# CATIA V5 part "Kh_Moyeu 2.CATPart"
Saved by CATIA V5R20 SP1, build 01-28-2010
Part number: Moyeu 2
Bounding box of the stored display mesh (mm): x -31.991 to 31.991, y -32 to 32, z -27 to 27
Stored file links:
  G:\Khaled_CFAO_2011\SIL\SIL_GR1\tmerino\Khaled\CAD_Thinkmotion\Kh_Moyeu 2.CATPart
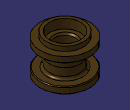
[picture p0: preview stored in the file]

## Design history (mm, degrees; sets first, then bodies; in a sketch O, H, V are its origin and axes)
Body1 (main body)
  Sketch1 on yz-plane, origin (0, 0, 0), H (0, 1, 0), V (0, 0, 1)
    line L1 (13, 0) -> (13, 15)
    point P1 (13, 0)
    point P2 (13, 15)
    line L2 (13, 15) -> (20, 15)
    point P3 (20, 15)
    line L3 (20, 15) -> (20, 27)
    point P4 (20, 27)
    line L4 (20, 27) -> (24, 27)
    point P5 (24, 27)
    line L5 (24, 27) -> (24, 21)
    point P6 (24, 21)
    line L6 (24, 21) -> (32, 21)
    point P7 (32, 21)
    line L7 (32, 21) -> (32, 13)
    point P8 (32, 13)
    line L8 (32, 13) -> (20, 13)
    point P9 (20, 13)
    line L9 (20, 13) -> (20, 0)
    point P10 (20, 0)
    point P11 (13, 0)
    point P12 (13, -15)
    point P13 (20, -15)
    point P14 (20, -27)
    point P15 (24, -27)
    point P16 (24, -21)
    point P17 (32, -21)
    point P18 (32, -13)
    point P19 (20, -13)
    point P20 (20, 0)
    line L10 (13, 0) -> (13, -15)
    line L11 (13, -15) -> (20, -15)
    line L12 (20, -15) -> (20, -27)
    line L13 (20, -27) -> (24, -27)
    line L14 (24, -27) -> (24, -21)
    line L15 (24, -21) -> (32, -21)
    line L16 (32, -21) -> (32, -13)
    line L17 (32, -13) -> (20, -13)
    line L18 (20, -13) -> (20, 0)
    distance L1 V = 13
    length L1 = 15
    distance L3 V = 20
    length L3 = 12
    length L4 = 4
    length L5 = 6
    length L6 = 8
    length L7 = 8
    length L8 = 12
    vertical: L1 V, L3 V, L5 V, L7 V, L9 V
    horizontal: L2 H, L4 H, L6 H, L8 H
    coincidence: P10 H, P1 P11, P10 P20
    symmetry: P1 P11 H, P2 P12 H, P3 P13 H, P4 P14 H, P5 P15 H, P6 P16 H, P7 P17 H, P8 P18 H, P9 P19 H, P10 P20 H, L1 L10 H, L2 L11 H, L3 L12 H, L4 L13 H, L5 L14 H, L6 L15 H, L7 L16 H, L8 L17 H, L9 L18 H
  Shaft1: profile Sketch1, axis Sketch1.V, angle 360
  Fillet1: radius 3, on edge [face of Shaft1 from Sketch1.L17 | face of Shaft1 from Sketch1.L18]; edge [face of Shaft1 from Sketch1.L9 | face of Shaft1 from Sketch1.L8]
  Chamfer1: length 2, angle 45, on edge [face of Shaft1 from Sketch1.L2 | face of Shaft1 from Sketch1.L1]; edge [face of Shaft1 from Sketch1.L10 | face of Shaft1 from Sketch1.L11]
  Chamfer2: length 1, angle 45, on edge [face of Shaft1 from Sketch1.L16 | face of Shaft1 from Sketch1.L17]; edge [face of Shaft1 from Sketch1.L8 | face of Shaft1 from Sketch1.L7]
